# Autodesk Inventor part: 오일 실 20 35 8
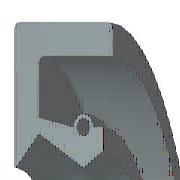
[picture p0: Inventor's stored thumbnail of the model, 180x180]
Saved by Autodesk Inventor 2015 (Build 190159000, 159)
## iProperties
IsCustomPart: 0
Created: 2018-09
Part Number: 오일 실 20 35 8
Material: 고무
Description: 오일-실
Document SubType Name: Modeling
Standard: KS B 2804
Standards Organization: KS
Language: ko-KR
Size Designation: D - 20 35 8
Categories: <MemberInstance><Categories><Category DisplayName="샤프트 부품" InternalName="7f7aeb1f-a693-4053-b835-cee3144e0d98" Mnemonic="SHFT"><Category DisplayName="실링" Intern
Density: 0.93 g/cm^3
Mass: 2.54606 g
Surface Area: 35.9421 cm^2
Volume: 2.7377 cm^3
Appearance: 고무 - 검은색 - 버전 1.1
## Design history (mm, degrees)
revolve "본체" stored, may be unused: angle "d17" = 90 deg
revolve "스프링1" stored, may be unused: angle "d18" = 90 deg
body "Solid1"
sketch "스케치1"
  geometry: L1 (0, 17.5)-(8, 17.5); L2 (8, 15.75)-(1.75, 15.75); L3 (1.75, 11.75)-(4.9, 10); L4 (4.9, 10)-(0, 10); L5 (0, 0)-(9.586, 0) reference; L6 (4.9, 10)-(6.3, 10.875); L7 (0, 18)-(0, -3) reference; L8 (-1.941, 0)-(11.507, 0) reference; L9 (4.2, 12.1)-(1.75, 12.71); L10 (1.75, 12.71)-(1.75, 15.75); L11 (0, 17.5)-(0, 10.088); L12 (4.9, 10)-(0, 10); L13 (1.75, 11.75)-(0.152, 10.028); L14 (8, 17.5)-(8, 15.75); L15 (5.6, 12.1)-(6.3, 12.1); L16 (6.3, 12.1)-(6.3, 10.875); C1 r 0.455 at (4.9, 12.1); A1 r 0.7 centre (4.9, 12.1) between (5.6, 12.1) and (4.2, 12.1); A2 r 0.088 centre (0.088, 10.088) between (0, 10.088) and (0.152, 10.028); 1 further point
  constraints: 28 end point, 5 horizontal alignment, 5 point on line, 4 point on circle, 4 vertical alignment, 3 centre point, 3 tangent, 2 collinear, 2 horizontal, 2 perpendicular, 1 coincident, 1 parallel
  dimensions: "d0" = 35 diameter of L1 L5 (= SD2); "d1" = 1.75 distance of L1.end L2.start (= SD); "d2" = 0.91 diameter of C1 (= SPDI); "d3" = 1.4 diameter of A1 (= SPDA); "d4" = 20 diameter of L3.end L5 (= NND); "d5" = 23.5 diameter of L3.start L5 (= TKDM); "d7" = 25.42 diameter of L9.end L5 (= TKDM + 0.24 x SWDT); "d8" = 1.75 distance between parallel lines of L11 L10 (= SD); "d9" = 4.9 distance from line of L11 C1.centre (= SPDST); "d10" = 24.2 diameter of C1.centre L5 (= HLDM); "d11" = 0.0875 radius of A2 (= 0.25 x LAB); "d12" = 6.3 distance between parallel lines of L11 L16 (= SDI); "d13" = 21.75 diameter of L6.end L5 (= ABDM); "d14" = 8 distance from line of L11 L1.end (= SWDT)
fillet "모깎기1" dims "d6" = 0.3 (= RR)
other parameters: "SD2" = 35 [user parameter; used in 1 equation term], "SWDT" = 8 [user parameter; used in 2 equation terms], "RR" = 0.3 [user parameter; used in 1 equation term], "SD" = 1.75 [user parameter; used in 2 equation terms], "NND" = 20 [user parameter; used in 1 equation term], "SPDA" = 1.4 [user parameter; used in 1 equation term], "SPDI" = 0.91 [user parameter; used in 1 equation term], "TKDM" = 23.5 [user parameter; used in 2 equation terms], "HLDM" = 24.2 [user parameter; used in 1 equation term], "ABDM" = 21.75 [user parameter; used in 1 equation term], "SDI" = 6.3 [user parameter; used in 1 equation term], "SPDST" = 4.9 [user parameter; used in 1 equation term], "LAB" = 0.35 [user parameter; used in 1 equation term], "d15" = 0, "d16" = 0, "d19" = 0
